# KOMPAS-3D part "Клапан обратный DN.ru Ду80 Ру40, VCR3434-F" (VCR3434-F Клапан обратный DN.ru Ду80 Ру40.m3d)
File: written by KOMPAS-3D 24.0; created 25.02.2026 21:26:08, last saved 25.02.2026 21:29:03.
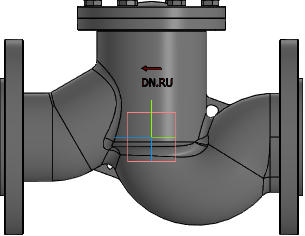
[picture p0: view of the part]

Document properties: Автор: R2D2; Полное имя файла: VCR3434-F Клапан обратный DN.ru Ду80 Ру40.cdw

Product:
- Part/product: Клапан обратный DN.ru Ду80 Ру40  | designation VCR3434-F
    Масса: 22
    Раздел спецификации: Прочие изделия
    Форматы листов документа: A2
    Примечание: D100-04057
    additional columns: D100-04057

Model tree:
1. Операция без истории:2

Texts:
  Грань.Твердое тело1
  Точка начала. Х
  Точка начала. Y
  Точка начала. Z
  VCR3434-F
